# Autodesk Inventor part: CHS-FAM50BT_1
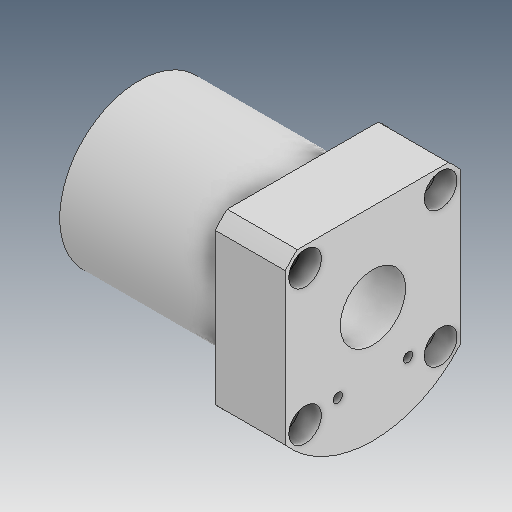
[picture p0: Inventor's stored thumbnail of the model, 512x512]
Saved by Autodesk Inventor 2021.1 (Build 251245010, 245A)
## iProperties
Created: 2019-04
Part Number: CHS-FAM50BT_1
Material: Ogólny
Document SubType Name: Modeling
Designer: user
Density: 1 g/cm^3
Appearance: Domyślna
Author: user
Revision Number: ÈÎºÎ
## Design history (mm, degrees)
feature "ÊäÈë1"
node "Bryła1"
